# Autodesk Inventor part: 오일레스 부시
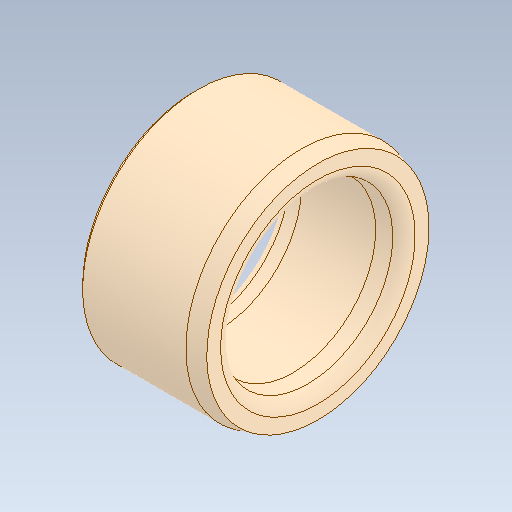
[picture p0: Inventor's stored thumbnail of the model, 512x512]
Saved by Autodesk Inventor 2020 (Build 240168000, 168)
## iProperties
Created: 2024-07
Part Number: 오일레스 부시
Material: 일반
Document SubType Name: Modeling
Designer: oem
Density: 1 g/cm^3
Appearance: 기본값
Author: jhkim
Sending System: Autodesk Inventor 2025
Preprocessor: ST-DEVELOPER v20
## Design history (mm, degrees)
feature "솔리드1"
node "솔리드2"
